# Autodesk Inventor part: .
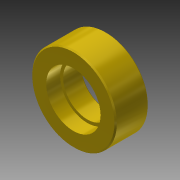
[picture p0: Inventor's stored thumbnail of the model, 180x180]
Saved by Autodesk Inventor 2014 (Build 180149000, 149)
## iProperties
Created: 2002-09
Part Number: .
Description: b_holder.ipt.
Document SubType Name: Modeling
Density: 1 g/cm^3
Material: Generic
Appearance: Glossy - Gold
ProtocolID: P00020918101010621
Protocol: P00020918101010621<@PID>[Version]<@EL>Version=2.2<@EL>[Synchronize]<@EL>ChangedVars=<@EL>[BaseView]<@EL>EnableUpdate=<@EL>UpdateAll=0<@EL>OnTop=0<@EL>Left=337<@
Control State: 0
Master: False
Checked Out: False
Shininess: 64.0
Length Units: 11269
Angle Units: 11279
Time Units: 11290
Mass Units: 11283
Length Display Precision: 3
Angle Display Precision: 2
Density: 0.0
Volumn: 0.0
Area: 0.0
PropertySet Name: Model Information
Author: PaulN
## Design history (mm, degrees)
sketch "Sketch1"
  geometry: C1 r 70 at (177, 181.5); C2 r 45 at (177, 181.5)
  constraints: 2 centre point, 1 coincident
  dimensions: "D_Out" = 90 diameter of C2; "DIAM_OUT" = 140 diameter of C1
extrude "Extrusion1" new body sketch "Sketch1" distance "d1" = 55; taper "d2" = 0 deg
workplane "Work Plane1"
sketch "Sketch2"
  geometry: C1 r 45 at (0, 0) reference; C2 r 40 at (0, 0)
  constraints: 1 centre point, 1 coincident
  dimensions: "d4" = 5 radial gap between concentric circles of C1 C2
extrude "Extrusion2" join sketch "Sketch2" stored distance "d5" = 60; taper "d6" = 0 deg
chamfer "Chamfer1" distance "d7" = 2; stored, may be unused: second distance "d8" = 2, angle "d10" = 45 deg
body "Solid1"
other parameters: "d3" = -23 (= -B), "B" = 23 [user parameter; used in 1 equation term]
